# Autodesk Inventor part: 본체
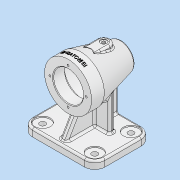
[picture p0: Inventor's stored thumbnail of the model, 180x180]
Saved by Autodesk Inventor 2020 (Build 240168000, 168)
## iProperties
Created: 2024-12
Part Number: 본체
Material: 알루미늄 6061
Document SubType Name: Modeling
Designer: 1강의실14
Density: 2.7 g/cm^3
Appearance: 알루미늄 - 평지
Mass: 746.526 g
Surface Area: 672.205 cm^2
Volume: 276.491 cm^3
Author: 1강의실14
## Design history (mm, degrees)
sketch "스케치2"
  geometry: C1 r 37 at (0, 0); 1 further point
  constraints: 1 centre point, 1 coincident
  dimensions: "d15" = 74 diameter of C1
extrude "돌출1" new body sketch "스케치2" distance "d16" = 20; taper "d17" = 0 deg
sketch "스케치3"
  geometry: L1 (-37, -20)-(37, -20) reference; L2 (0, -20)-(0, -84); L3 (0, -84)-(21, -84); L4 (21, -84)-(37, -20); L5 (37, -20)-(0, -20); 1 further point
  constraints: 8 end point, 1 collinear, 1 horizontal, 1 midpoint
  dimensions: "d19" = 64 distance of L2.start L2.end; "d22" = 21 distance of L2.end L3.end; "d24" = 42 diameter of L3.end L2
revolve "회전1" sketch "스케치3" stored, may be unused: angle "d25" = 90 deg
sketch "스케치4"
  geometry: L1 (0, 0)-(0, -76); L2 (-21, -84)-(21, -84) reference; L3 (37, 0)-(-37, 0) reference; L4 (23.5, 0)-(23.5, -18); L5 (23.5, -18)-(25.596, -18); L6 (30.447, -24.213)-(21.318, -60.728); L7 (18.408, -63)-(18.5, -63); L8 (17.5, -64)-(17.5, -72.7); L9 (17.2, -73)-(15.5, -73); L10 (15.5, -73)-(15.5, -73); L11 (12.5, -76)-(0, -76); L12 (37, -20)-(21, -84) reference; L13 (18.5, -63)-(17.5, -64); L14 (23.5, 0)-(0, 0); A1 r 0.3 centre (17.2, -72.7) between (17.2, -73) and (17.5, -72.7); A2 r 5 centre (25.596, -23) between (30.447, -24.213) and (25.596, -18); A3 r 3 centre (18.408, -60) between (18.408, -63) and (21.318, -60.728); A4 r 3 centre (12.5, -73) between (12.5, -76) and (15.5, -73); 3 further points
  constraints: 22 end point, 8 point on circle, 8 tangent, 6 perpendicular, 5 point on line, 4 centre point, 2 parallel, 1 collinear
  dimensions: "d26" = 31 diameter of L10 L1; "d27" = 35 diameter of L8 L1; "d28" = 47 diameter of L4 L1; "d30" = 64 diameter of point (32, -18) L1; "d32" = 18 distance between parallel lines of L5 L3; "d33" = 45 distance between parallel lines of L7 L5; "d34" = 10 distance between parallel lines of L9 L7; "d35" = 3 distance between parallel lines of L11 L9; "d36" = 0.3 radius of A1 (derived); "d37" = 5 radius of A2 (derived); "d38" = 3 radius of A3 (derived); "d39" = 1 distance of L7.end point (17.5, -63); "d40" = 1 distance of L8.start point (17.5, -63) (= d39); "d41" = 3 radius of A4
revolve "회전2" stored, may be unused: angle "d42" = 360 deg
node "작업 평면1"
sketch "스케치5"
  geometry: L1 (57, -74)-(-57, -74); L2 (-57, -74)-(-57, 15); L3 (-57, 15)-(57, 15); L4 (57, 15)-(57, -74); L5 (37, 0)-(-37, 0) reference; 1 further point
  constraints: 8 end point, 2 parallel, 1 horizontal, 1 perpendicular
  dimensions: "d45" = 114 distance between parallel lines of L2 L4; "d46" = 89 distance between parallel lines of L3 L1; "d47" = 57 distance from line of L4 point (0, 0); "d50" = 15 distance between parallel lines of L3 L5
extrude "돌출2" join sketch "스케치5" distance "d48" = 12; taper "d49" = 0 deg
sketch "스케치6"
  geometry: L1 (-28, 45)-(28, 45); L2 (28, 45)-(28, 37); L3 (28, 37)-(-28, 37); L4 (-28, 37)-(-28, 45); L5 (57, 74)-(-57, 74) reference; 1 further point
  constraints: 8 end point, 2 parallel, 1 horizontal, 1 perpendicular
  dimensions: "d51" = 8 distance between parallel lines of L3 L1; "d52" = 56 distance between parallel lines of L2 L4; "d53" = 28 distance from line of L4 point (0, 0); "d54" = 29 distance between parallel lines of L1 L5
extrude "돌출3" join sketch "스케치6" stored distance "d55" = 12; taper "d56" = 0 deg
sketch "스케치7"
  geometry: L1 (-21, -84)-(21, -84) reference; L2 (-37, -20)-(37, -20) reference; L3 (-16.987, -37)-(-16.987, -37) reference; L4 (-12.711, -45)-(-12.711, -45) reference; L5 (-70, -74)-(-70, 15) reference; L6 (-37, -20)-(-21, -84) reference; L7 (-37, -11.053)-(-70, 8); L8 (-82, 15)-(-70, 15) reference; L9 (-37, -20)-(37, -20) reference; L10 (37, 0)-(-37, 0) reference; L11 (-37, 0)-(-37, -20) reference; 1 further point
  constraints: 2 end point, 2 point on line, 2 other
  dimensions: "d57" = 60 deg angle of L7 L5; "d58" = 7 distance from line of L8 L7.end
feature "리브1" sketch "스케치7" dims "d59" = 1, "d60" = 10, "d61" = 0, "d62" = 0, "d63" = 1, "d64" = 1
sketch "스케치8"
  geometry: L1 (-30.75, -45)-(-21, -84) reference; L2 (-82, -74)-(-70, -74) reference; L3 (-70, -74)-(-23.5, -74); 1 further point
  constraints: 2 end point, 1 collinear, 1 point on line
feature "리브2" sketch "스케치8" dims "d65" = 1, "d66" = 10, "d67" = 0, "d68" = 0, "d69" = 1, "d70" = 1
node "작업 평면3"
sketch "스케치10"
  geometry: L1 (0, -66)-(0, -9.888); L2 (10, -56)-(10, -19.888); L3 (-10, -19.888)-(-10, -56); L4 (37, 0)-(-37, 0) reference; L5 (-5, -11.249)-(-5, -20) reference; L6 (5, -20)-(-5, -20) reference; L7 (5, -20)-(5, -11.249) reference; L8 (37, 0)-(-37, 0) reference; A1 r 10 centre (0, -56) between (-10, -56) and (10, -56); A2 r 10 centre (0, -19.888) between (10, -19.888) and (-10, -19.888); 3 further points; 1 other entity
  constraints: 8 end point, 6 point on circle, 4 tangent, 2 centre point, 2 point on line, 1 midpoint, 1 parallel, 1 vertical, 1 other
  dimensions: "d77" = 20 diameter of A2; "d79" = 56 distance from line of L4 A1.centre; "d80" = 10 distance from line of L2 point (0, 0); "d81" = 56 distance of A1.centre point (0, 0)
  node "투영된 루프3"
sketch "스케치11"
  geometry: L1 (57, 74)-(-57, 74) reference; 5 further points
  constraints: 2 horizontal alignment, 2 vertical alignment
  dimensions: "d84" = 16 distance from line of point (41, 58) L1; "d85" = 57 distance of point (41, 1) point (41, 58); "d86" = 82 distance of point (-41, 58) point (41, 58); "d87" = 41 horizontal distance of point (41, 58) point (0, 0)
hole "구멍1" sketch "스케치11" at (-41, 58), (41, 58), (41, 1), (-41, 1) diameter "d88" = 9; stored, may be unused: countersink angle "d92" = 82 deg, drill point angle "d94" = 0 deg; dims "d89" = 6, "d90" = 24, "d91" = 2, "d93" = 12
extrude "돌출6" join sketch "스케치10" distance "d97" = 10; taper "d98" = 0 deg
revolve "회전3" stored, may be unused: angle "d99" = 90 deg
revolve "회전4" stored, may be unused: angle "d100" = 90 deg
sketch "스케치13" dims "d101" = 57
  geometry: 3 further points
  constraints: 2 vertical alignment, 1 coincident, 2 other
hole "구멍2" sketch "스케치13" at (0, 28.5) diameter "d102" = 3.242; stored, may be unused: countersink angle "d106" = 82 deg, drill point angle "d108" = 120 deg; dims "d103" = 8, "d104" = 24, "d105" = 2, "d107" = 10
node "작업 평면4"
sketch "스케치14"
  geometry: L1 (37, 0)-(-37, 0) reference; 3 further points
  constraints: 1 midpoint, 1 vertical alignment, 1 other
  dimensions: "d112" = 9 distance from line of point (0, -9) L1
feature "엠보싱1" sketch "스케치14" dims "d113" = 0.5, "d114" = 0
fillet "모깎기1" dims "d115" = 3
fillet "모깎기2" dims "d116" = 3
fillet "모깎기3" dims "d117" = 16
fillet "모깎기4" dims "d118" = 3
sketch "스케치15"
  geometry: A1 r 10 centre (0, 56) between (10, 56) and (-10, 56) reference; 2 further points
  constraints: 1 coincident
hole "구멍3" sketch "스케치15" at (0, 56) diameter "d119" = 5.1881; stored, may be unused: countersink angle "d123" = 82 deg, drill point angle "d125" = 120 deg; dims "d120" = 15, "d121" = 10, "d122" = 1, "d124" = 16
fillet "모깎기6" dims "d127" = 3
fillet "모깎기7" dims "d128" = 3
chamfer "모따기1" distance "d129" = 1; stored, may be unused: second distance "d130" = 2, angle "d131" = 45 deg
node "솔리드1"
pattern_circular "원형 패턴1" dims angle "d110" = 360 deg
node "투영된 루프1"
node "투영된 루프2"
feature "A9D066F2-1C7D-4E18-AEED-F7BC21143FA4" dims "d88" = 9, "d89" = 6, "d90" = 24, "d91" = 2, "d92" = 82 deg, "d93" = 12, "d94" = 0
other parameters: "d43" = -82, "d76" = -115
